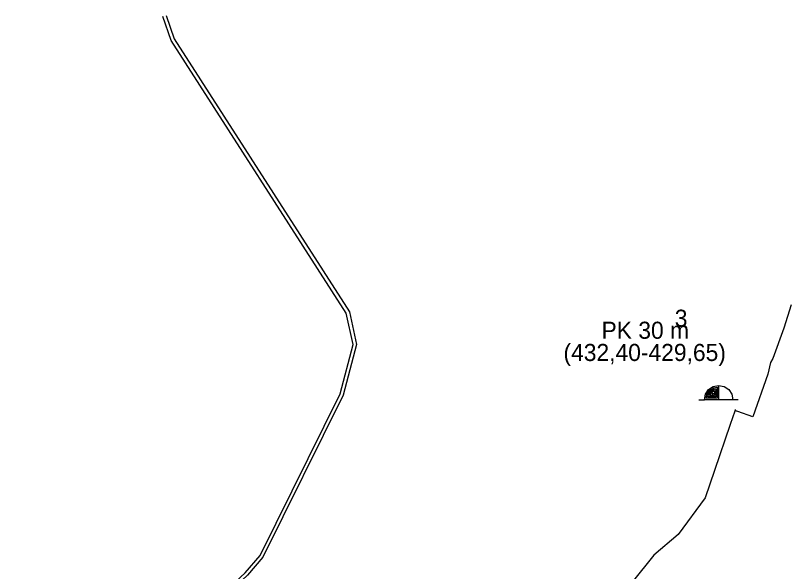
# Model space of a CAD drawing. Extents: x -445050 to -433212, y -1145927 to -1129778.
# Drawn here: x -442653.1 to -442200.7, y -1130531.1 to -1130205.6 of the extents above; entities that cross this region are included whole.
import ezdxf

# ---------------------------------------------------------------- set-up
doc = ezdxf.new("R2010")
doc.units = 0
for name, color, linetype in [('Vrstva 14', 7, 'Continuous'), ('Vrstva 3', 7, 'Continuous'), ('Vrstva 53', 7, 'Continuous')]:
    doc.layers.add(name, color=color, linetype=linetype)

msp = doc.modelspace()

# ---------------------------------------------------------------- linework, layer by layer
at = {"layer": 'Vrstva 14'}
for p, q in [((-442252.6, -1130430.47), (-442249.44, -1130430.47)), ((-442229.56, -1130430.47), (-442232.72, -1130430.47))]:
    msp.add_line(p, q, dxfattribs=at)
for points in [[(-442249.44, -1130430.47), (-442248.8, -1130427.27), (-442246.99, -1130424.56), (-442244.28, -1130422.75), (-442241.08, -1130422.11), (-442241.08, -1130430.47)], [(-442248.47, -1130429.67), (-442248.05, -1130427.58), (-442246.41, -1130425.13), (-442243.97, -1130423.5), (-442241.88, -1130423.08), (-442241.88, -1130429.67)], [(-442247.49, -1130428.87), (-442247.3, -1130427.89), (-442245.84, -1130425.71), (-442243.65, -1130424.25), (-442242.68, -1130424.06), (-442242.68, -1130428.87)], [(-442245.26, -1130426.29), (-442243.48, -1130425.1), (-442243.48, -1130428.07), (-442246.45, -1130428.07)], [(-442244.95, -1130427.27), (-442244.68, -1130426.86), (-442244.28, -1130426.59), (-442244.28, -1130427.27)]]:
    msp.add_lwpolyline(points, close=True, dxfattribs=at)
msp.add_lwpolyline([(-442241.08, -1130422.11), (-442237.88, -1130422.75), (-442235.17, -1130424.56), (-442233.36, -1130427.27), (-442232.72, -1130430.47), (-442241.08, -1130430.47)], dxfattribs=at)
at = {"layer": 'Vrstva 3'}
for points in [[(-442198.56, -1130374.88), (-442202.87, -1130388.52), (-442209.35, -1130406.46), (-442210.72, -1130408.63), (-442212.3, -1130415.55), (-442221.12, -1130440.55), (-442229.76, -1130437.46), (-442230.56, -1130437.23), (-442230.88, -1130437.09), (-442231.46, -1130436.89), (-442231.31, -1130436.49), (-442231.22, -1130436.26)], [(-442231.46, -1130436.89), (-442231.58, -1130437.28), (-442234.41, -1130444.99), (-442243.59, -1130471.96), (-442248.95, -1130488.01), (-442264.85, -1130509.33), (-442279.03, -1130521.58), (-442291.84, -1130537.23)]]:
    msp.add_lwpolyline(points, dxfattribs=at)
at = {"layer": 'Vrstva 53'}
for points in [[(-442568.35, -1130931.64), (-442521.13, -1130894.45), (-442507.21, -1130877.02), (-442523.31, -1130861.02), (-442563.69, -1130818.3), (-442595.51, -1130789.04), (-442653.05, -1130734.64), (-442619.17, -1130686.46), (-442611.12, -1130666.31), (-442601.97, -1130626.02), (-442591.72, -1130607.71), (-442574.88, -1130584.27), (-442518.52, -1130531.89), (-442509.74, -1130521.64), (-442462.89, -1130427.14), (-442455.21, -1130398.2), (-442459.23, -1130379.89), (-442561.86, -1130220.16), (-442566.66, -1130206.21)], [(-442564.77, -1130205.56), (-442560.04, -1130219.28), (-442457.35, -1130379.11), (-442453.15, -1130398.25), (-442461.01, -1130427.85), (-442508.06, -1130522.75), (-442517.08, -1130533.28), (-442573.38, -1130585.6), (-442590.03, -1130608.78), (-442600.08, -1130626.75), (-442609.2, -1130666.91), (-442617.4, -1130687.42), (-442650.42, -1130734.37), (-442594.15, -1130787.58), (-442562.28, -1130816.88), (-442521.88, -1130859.62), (-442504.53, -1130876.87), (-442519.71, -1130895.88), (-442567.11, -1130933.21)]]:
    msp.add_lwpolyline(points, dxfattribs=at)

# ---------------------------------------------------------------- texts
at = {"layer": 'Vrstva 14'}
for s, p in [('3', (-442266.79, -1130387.79)), ('      PK 30 m', (-442331.99, -1130394.83)), ('(432,40-429,65)', (-442331.99, -1130407.83))]:
    msp.add_text(s, height=10, dxfattribs=at).set_placement(p)

doc.saveas('drawing.dxf')
